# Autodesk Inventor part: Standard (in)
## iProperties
Shininess: 64.0
Length Units: 11272
Angle Units: 11279
Time Units: 11290
Mass Units: 11286
Length Display Precision: 3
Angle Display Precision: 2
Compacted: True
Part Number: Standard (in)
Document SubType Name: Modeling
Created: 2002-08
Density: 0.0
Volumn: 0.0
Area: 0.0
PropertySet Name: Model Information
Control State: 0
Master: False
Checked Out: False
